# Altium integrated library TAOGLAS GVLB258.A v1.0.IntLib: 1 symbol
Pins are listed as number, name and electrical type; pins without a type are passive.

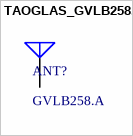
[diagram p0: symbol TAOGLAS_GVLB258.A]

## TAOGLAS_GVLB258.A
designator ANT?, comment GVLB258.A
Single Feed Stacked Patch Antenna for GNSS L1 / L5, GLONASS, BeiDou B1/B2a; ComponentLibStatus: Created; MFG: Taoglas; Temp_High: +85C; Temp_Low: -40C
footprint TAOGLAS_GVLB258.A (Single Feed Stacked Patch Antenna for GNSS L1 / L5, GLONASS, BeiDou B1)
pins: 1 RF FEED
